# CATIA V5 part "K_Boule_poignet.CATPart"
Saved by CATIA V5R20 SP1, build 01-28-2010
Part number: boule_poignet
Bounding box of the stored display mesh (mm): x -20 to 20, y -20 to 20, z -20.927 to 19.073
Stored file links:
  G:\Khaled_CFAO_2011\SIL\SIL_GR1\mroland\Khaled\CAD_CATIA_Modifie\K_Boule_poignet.CATPart
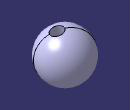
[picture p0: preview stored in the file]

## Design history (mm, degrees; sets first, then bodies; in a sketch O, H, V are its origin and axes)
Set1
  Sketch1 on zx-plane, origin (0, 0, 0), H (-1, 0, 0), V (0, 0, 1)
    point P1 (0, 19.0731)
    line L1 (0, 19.0731) -> (0, -20.9269)
    arc A1 centre (0, -0.9269) radius 20 from (0, -20.9269) to (0, 19.0731) ccw
    point P3 (0, -0.9269)
    point P4 (19.9785, 0)
    radius A1 = 20
    coincidence: P1 V, A1 P4, P4 H, P3 L1
    vertical: L1 V
    fix: A1
Body1 (main body)
  Shaft1: profile Sketch1, axis Sketch1.L1, angle 360
  Sketch2 on {plane type Tangent, Support face of Shaft1 from Sketch1.A1, RefPoint {point type OnSurface, Support face of Shaft1 from Sketch1.A1, RefPoint {point stored without definition}, Length 0, Direction (0, 991.8495, 127.4147)}}, origin (4.5427, -2.4817, 18.3916), H (0.9739, 0.0289, -0.2253), V (0, -0.9918, -0.1274)
    point P1 (0, 0)
  Hole1: placed by Sketch2, at (4.5427, -2.4817, 18.3916) direction (-0.2271, 0.1241, -0.9659), diameter 10, through (limit type 3)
